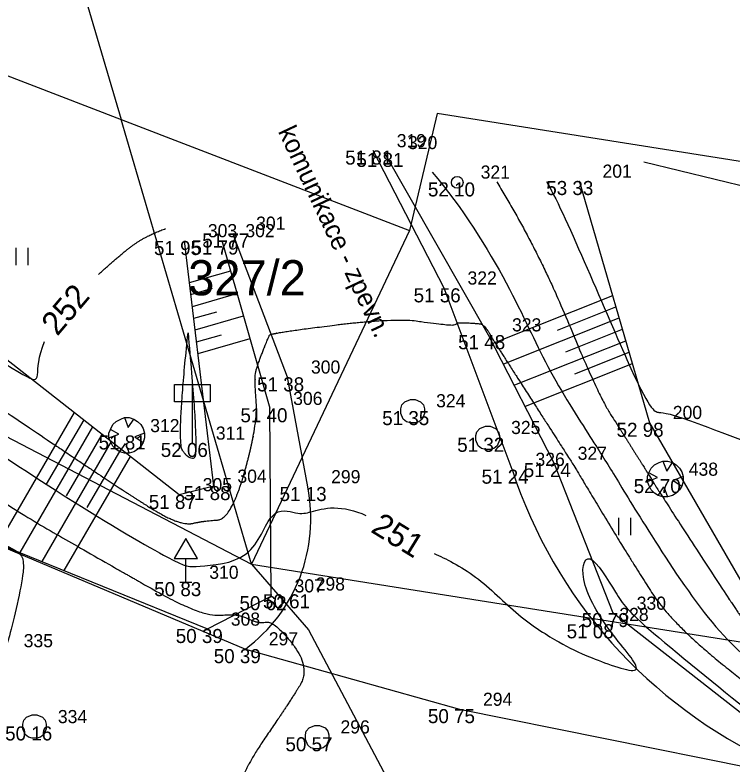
# Model space of a CAD drawing. Extents: x -704057 to -703795, y -1008732 to -1008584.
# Drawn here: x -703998.45 to -703983.13, y -1008647.96 to -1008631.96 of the extents above; entities that cross this region are included whole.
import ezdxf

# ---------------------------------------------------------------- set-up
doc = ezdxf.new("R2010")
doc.units = 0
for name, color, linetype in [('Z_body', 7, 'Continuous'), ('Z_body_cisla', 7, 'Continuous'), ('Z_body_vysky', 7, 'Continuous'), ('Z_dopravni_znaceni', 7, 'Continuous'), ('Z_katastr_cisla_pozemkove', 7, 'Continuous'), ('Z_katastr_hranice', 7, 'Continuous'), ('Z_katastr_hranice_KU', 7, 'Continuous'), ('Z_katastr_vnitrni_kresba', 7, 'Continuous'), ('Z_komunikace_zpevn_pl', 7, 'Continuous'), ('Z_popis', 7, 'Continuous'), ('Z_site_znaky_kanalizace', 7, 'Continuous'), ('Z_sloupky_ocel', 7, 'Continuous'), ('Z_teren_hrany_paty', 7, 'Continuous'), ('Z_vrstevnice_hlavni', 7, 'Continuous'), ('Z_vrstevnice_popis', 7, 'Continuous'), ('Z_vrstevnice_vedlejsi', 7, 'Continuous'), ('Z_zelen_jednotliva', 7, 'Continuous')]:
    doc.layers.add(name, color=color, linetype=linetype)

# ---------------------------------------------------------------- blocks, each defined once
blk = doc.blocks.new('POINT_DISPLAY')
blk.add_line((0, 0), (0, 0))
blk = doc.blocks.new('Z23')
for p, q in [((-0.23, 0.3), (-0.13, 0.35)), ((-0.13, 0.35), (-0.05, 0.38)), ((-0.05, 0.38), (0.05, 0.38)), ((-0.05, 0.38), (0.03, 0.17)), ((0.03, 0.17), (0.15, 0.35)), ((0.05, 0.38), (0.15, 0.35)), ((0.15, 0.35), (0.23, 0.3)), ((-0.35, 0.13), (-0.3, 0.23)), ((-0.3, 0.23), (-0.23, 0.3)), ((0.23, 0.3), (0.3, 0.23)), ((0.3, 0.23), (0.35, 0.15)), ((-0.38, 0.05), (-0.35, 0.13)), ((-0.38, -0.05), (-0.38, 0.05)), ((-0.38, -0.05), (-0.17, 0.03)), ((-0.17, 0.03), (-0.35, 0.13)), ((0.38, 0.05), (0.17, -0.03)), ((0.35, 0.15), (0.38, 0.05)), ((0.38, 0.05), (0.38, -0.05)), ((-0.35, -0.13), (-0.38, -0.05)), ((-0.3, -0.23), (-0.35, -0.13)), ((0.17, -0.03), (0.35, -0.15)), ((0.35, -0.15), (0.3, -0.23)), ((0.38, -0.05), (0.35, -0.15)), ((-0.23, -0.3), (-0.3, -0.23)), ((-0.15, -0.35), (-0.23, -0.3)), ((-0.15, -0.35), (-0.03, -0.17)), ((-0.03, -0.17), (0.05, -0.38)), ((0.23, -0.3), (0.15, -0.35)), ((0.3, -0.23), (0.23, -0.3)), ((-0.05, -0.38), (-0.15, -0.35)), ((0.05, -0.38), (-0.05, -0.38)), ((0.15, -0.35), (0.05, -0.38))]:
    blk.add_line(p, q)
blk = doc.blocks.new('Z620')
for p, q in [((-0.23, 0.13), (-0.17, 0.2)), ((-0.17, 0.2), (-0.05, 0.25)), ((-0.05, 0.25), (0.05, 0.25)), ((0.05, 0.25), (0.17, 0.2)), ((0.17, 0.2), (0.23, 0.13)), ((-0.25, 0.05), (-0.23, 0.13)), ((-0.25, -0.05), (-0.25, 0.05)), ((0.23, 0.13), (0.25, 0.05)), ((0.25, 0.05), (0.25, -0.05)), ((-0.2, -0.17), (-0.25, -0.05)), ((0.25, -0.05), (0.2, -0.17)), ((-0.13, -0.23), (-0.2, -0.17)), ((-0.05, -0.25), (-0.13, -0.23)), ((0.05, -0.25), (-0.05, -0.25)), ((0.13, -0.23), (0.05, -0.25)), ((0.2, -0.17), (0.13, -0.23))]:
    blk.add_line(p, q)
blk = doc.blocks.new('Z527')
for p, q in [((0, 0.93), (-0.25, 0.5)), ((0.25, 0.5), (0, 0.93)), ((-0.25, 0.5), (0.25, 0.5)), ((0, 0), (0, 0.5)), ((-0.13, 0), (0.13, 0))]:
    blk.add_line(p, q)
blk = doc.blocks.new('Z57')
for p, q in [((-0.38, 1.25), (0.38, 1.25)), ((-0.38, 0.88), (-0.38, 1.25)), ((0, 0), (0, 1.25)), ((0.38, 1.25), (0.38, 0.88)), ((0.38, 0.88), (-0.38, 0.88))]:
    blk.add_line(p, q)
blk = doc.blocks.new('Z15')
blk.add_circle((0, 0), 0.125)
blk = doc.blocks.new('Z306')
for p, q in [((-0.13, 0.17), (-0.13, -0.2)), ((0.13, 0.17), (0.13, -0.2))]:
    blk.add_line(p, q)

msp = doc.modelspace()

# ---------------------------------------------------------------- linework, layer by layer
at = {"layer": 'Z_katastr_hranice'}
for p, q in [((-704002.96, -1008611.05), (-703996.18, -1008634.19)), ((-703989.44, -1008634.06), (-703990.03, -1008636.56)), ((-703948.06, -1008640.63), (-703989.44, -1008634.06)), ((-703996.18, -1008634.19), (-703990.03, -1008636.56)), ((-703993.4, -1008643.68), (-703996.18, -1008634.19)), ((-703990.03, -1008636.56), (-703993.4, -1008643.68)), ((-703993.4, -1008643.68), (-703944.4, -1008651.45))]:
    msp.add_line(p, q, dxfattribs=at)
at = {"layer": 'Z_katastr_hranice_KU'}
for p, q in [((-703999.92, -1008640.28), (-703993.4, -1008643.68)), ((-703993.4, -1008643.68), (-703992.18, -1008645.08)), ((-703992.18, -1008645.08), (-703989.65, -1008649.86))]:
    msp.add_line(p, q, dxfattribs=at)
at = {"layer": 'Z_katastr_vnitrni_kresba'}
msp.add_line((-704003.46, -1008631.38), (-703996.18, -1008634.19), dxfattribs=at)
at = {"layer": 'Z_komunikace_zpevn_pl'}
for p, q in [((-703989.29, -1008637.79), (-703990.8, -1008634.85)), ((-703992.63, -1008639.69), (-703993.8, -1008636.62)), ((-703987.84, -1008641.66), (-703989.29, -1008637.79)), ((-703992.2, -1008642.03), (-703992.63, -1008639.69)), ((-704000.17, -1008642.69), (-703993.53, -1008645.49)), ((-703993.53, -1008645.49), (-703988.96, -1008646.77)), ((-703988.96, -1008646.77), (-703980.49, -1008648.48))]:
    msp.add_line(p, q, dxfattribs=at)
for centre, radius, start, end in [((-703977.91, -1008638.41), 10.448, 198.1269, 245.2768), ((-703995.6, -1008642.71), 3.467, 306.6532, 11.294)]:
    msp.add_arc(centre, radius, start, end, dxfattribs=at)
at = {"layer": 'Z_teren_hrany_paty'}
for p, q in [((-703988.34, -1008638.79), (-703990.56, -1008634.9)), ((-703986.41, -1008635.5), (-703984.91, -1008640.66)), ((-703994.2, -1008642.01), (-703994.83, -1008636.78)), ((-703994.03, -1008636.77), (-703993.01, -1008640.35)), ((-703994.94, -1008642.2), (-704001.6, -1008636.98)), ((-703994.72, -1008637.67), (-703993.84, -1008637.42)), ((-703994.69, -1008637.92), (-703994.23, -1008637.79)), ((-703994.66, -1008638.18), (-703993.71, -1008637.9)), ((-703985.7, -1008637.95), (-703988.25, -1008638.97)), ((-703985.63, -1008638.19), (-703986.88, -1008638.69)), ((-703994.63, -1008638.43), (-703994.14, -1008638.29)), ((-703994.6, -1008638.68), (-703993.57, -1008638.38)), ((-703985.56, -1008638.43), (-703988.02, -1008639.41)), ((-703985.49, -1008638.67), (-703986.7, -1008639.15)), ((-703994.57, -1008638.93), (-703994.04, -1008638.78)), ((-703994.54, -1008639.18), (-703993.43, -1008638.86)), ((-703986.94, -1008641.52), (-703988.34, -1008638.79)), ((-703985.42, -1008638.92), (-703987.79, -1008639.86)), ((-703985.35, -1008639.16), (-703986.51, -1008639.62)), ((-703985.28, -1008639.4), (-703987.56, -1008640.31)), ((-703997.18, -1008640.44), (-703998.81, -1008643.24)), ((-703992.98, -1008644.36), (-703993.01, -1008640.35)), ((-703996.98, -1008640.6), (-703997.78, -1008641.97)), ((-703996.79, -1008640.75), (-703998.34, -1008643.43)), ((-703984.91, -1008640.66), (-703982.03, -1008645.65)), ((-703996.59, -1008640.91), (-703997.35, -1008642.22)), ((-703996.39, -1008641.06), (-703997.87, -1008643.62)), ((-703996.19, -1008641.22), (-703996.91, -1008642.47)), ((-703995.99, -1008641.38), (-703997.4, -1008643.81)), ((-703985.68, -1008644.72), (-703986.94, -1008641.52)), ((-703994.2, -1008642.01), (-703994.94, -1008642.2)), ((-704000.17, -1008642.69), (-703994.34, -1008645.06)), ((-703994.34, -1008645.06), (-703992.98, -1008644.36)), ((-703982.11, -1008647.52), (-703985.68, -1008644.72))]:
    msp.add_line(p, q, dxfattribs=at)
at = {"layer": 'Z_vrstevnice_hlavni'}
msp.add_open_spline([(-703994.753, -1008638.739), (-703994.996, -1008641.052), (-703994.748, -1008641.441), (-703994.507, -1008641.397), (-703994.753, -1008638.739)], degree=2, dxfattribs=at)
at = {"layer": 'Z_vrstevnice_popis'}
for points, degree in [([(-704008.891, -1008633.225), (-704007.19, -1008634.58), (-704001.968, -1008637.528), (-704001.463, -1008637.527), (-703997.448, -1008640.245), (-703998.103, -1008639.589), (-703997.814, -1008638.926)], 3), ([(-704009.834, -1008633.947), (-704008.639, -1008634.898), (-704007.097, -1008636.135), (-704003.977, -1008638.277), (-704003.231, -1008638.819), (-704001.631, -1008639.907), (-704000.867, -1008639.906), (-703997.17, -1008642.409), (-703994.823, -1008643.756), (-703994.703, -1008643.728), (-703993.348, -1008643.651), (-703992.995, -1008642.406), (-703992.399, -1008642.624), (-703992.166, -1008642.575), (-703991.675, -1008642.426), (-703991.193, -1008642.529), (-703990.961, -1008642.637)], 3), ([(-704010.777, -1008634.669), (-704010.089, -1008635.217), (-704007.004, -1008637.69), (-704006.178, -1008638.257), (-704004.336, -1008639.596), (-704000.382, -1008642.286), (-704000.271, -1008642.286), (-703999.734, -1008642.649), (-703999.257, -1008642.923), (-703998.4, -1008643.409), (-703998.154, -1008643.54), (-703998.629, -1008645.519), (-703998.717, -1008645.615), (-703998.773, -1008645.668), (-703999.967, -1008646.451), (-704000.248, -1008646.631)], 3), ([(-703989.544, -1008635.313), (-703988.902, -1008636.056), (-703987.798, -1008637.865), (-703987.151, -1008639.438), (-703986.053, -1008641.144), (-703985.706, -1008641.697), (-703984.977, -1008642.908), (-703983.536, -1008645.121), (-703982.31, -1008646.105), (-703982.063, -1008646.423), (-703981.066, -1008646.966), (-703978.397, -1008647.285), (-703975.56, -1008647.648), (-703973.643, -1008647.827), (-703973.517, -1008647.838)], 3), ([(-703987.108, -1008635.508), (-703986.754, -1008636.087), (-703984.996, -1008640.365), (-703984.718, -1008640.456), (-703984.363, -1008640.44), (-703980.63, -1008641.987), (-703979.311, -1008641.778), (-703978.799, -1008641.628)], 3), ([(-703996.666, -1008637.496), (-703996.184, -1008637.054), (-703995.648, -1008636.67), (-703995.232, -1008636.515)], 2), ([(-703989.503, -1008643.449), (-703989.267, -1008643.557), (-703988.594, -1008643.878), (-703987.719, -1008644.81), (-703986.755, -1008645.399), (-703986.308, -1008645.619), (-703984.807, -1008646.186), (-703985.704, -1008645.225), (-703986.427, -1008644.081), (-703986.268, -1008643.227), (-703985.558, -1008644.406), (-703985.308, -1008644.79), (-703982.136, -1008647.335), (-703982.104, -1008647.377), (-703980.996, -1008647.981), (-703981.138, -1008648.096), (-703981.236, -1008648.238), (-703982.91, -1008647.991), (-703984.29, -1008649.466), (-703985.601, -1008651.032), (-703985.434, -1008652.571), (-703985.359, -1008653.111)], 3)]:
    msp.add_open_spline(points, degree=degree, dxfattribs=at)
at = {"layer": 'Z_vrstevnice_vedlejsi'}
msp.add_line((-703981.434, -1008635.969), (-703985.029, -1008635.098), dxfattribs=at)
for points in [[(-704009.362, -1008633.586), (-704007.915, -1008634.739), (-704007.143, -1008635.358), (-704002.876, -1008638.286), (-704002.679, -1008638.43), (-704002.255, -1008638.718), (-704001.165, -1008638.717), (-703995.889, -1008642.289), (-703994.89, -1008642.862), (-703994.417, -1008642.752), (-703993.832, -1008642.719), (-703993.258, -1008640.696), (-703993.341, -1008639.701), (-703993.272, -1008639.432), (-703993.04, -1008638.835), (-703992.99, -1008638.745), (-703990.403, -1008638.423), (-703989.481, -1008638.539), (-703989.058, -1008638.588), (-703989.018, -1008638.516), (-703988.578, -1008638.54), (-703988.475, -1008638.554), (-703988.362, -1008638.685), (-703988.319, -1008638.754), (-703988.294, -1008638.815), (-703986.637, -1008641.391), (-703986.518, -1008641.581), (-703985.267, -1008643.657), (-703984.422, -1008644.955), (-703982.223, -1008646.72), (-703982.083, -1008646.9), (-703980.47, -1008647.779), (-703979.335, -1008647.914), (-703971.793, -1008648.878), (-703969.312, -1008649.063), (-703968.076, -1008649.117), (-703960.948, -1008649.919), (-703959.282, -1008650.186), (-703958.493, -1008650.28), (-703957.367, -1008650.455), (-703955.116, -1008650.684), (-703950.816, -1008651.182), (-703948.3, -1008651.463), (-703946.953, -1008651.576), (-703945.397, -1008651.505), (-703943.023, -1008651.703), (-703939.161, -1008651.987), (-703938.27, -1008652.079), (-703937.191, -1008652.194), (-703934.147, -1008651.524), (-703931.028, -1008650.815), (-703930.717, -1008650.764), (-703928.94, -1008650.83), (-703928.501, -1008650.751), (-703928.424, -1008650.713), (-703928.413, -1008650.708), (-703928.266, -1008650.724), (-703926.027, -1008648.737), (-703920.5, -1008648.624), (-703915.824, -1008649.925), (-703908.88, -1008649.843), (-703904.651, -1008650.155), (-703897.103, -1008651.333), (-703893.743, -1008651.997), (-703889.99, -1008652.252), (-703881.693, -1008653.228), (-703874.656, -1008652.961), (-703868.448, -1008652.365), (-703859.857, -1008652.906), (-703856.36, -1008653.001), (-703843.765, -1008653.766), (-703842.17, -1008653.801), (-703841.143, -1008653.824), (-703831.904, -1008654.28)], [(-704010.305, -1008634.308), (-704009.364, -1008635.058), (-704007.05, -1008636.913), (-704005.077, -1008638.267), (-704003.784, -1008639.207), (-704001.007, -1008641.096), (-704000.569, -1008641.096), (-703998.452, -1008642.529), (-703996.572, -1008643.608), (-703994.455, -1008644.81), (-703993.69, -1008644.725), (-703993.267, -1008644.95), (-703992.917, -1008644.879), (-703992.134, -1008645.881), (-703992.595, -1008646.639), (-703993.503, -1008647.958), (-703993.68, -1008648.547), (-703995.276, -1008650.526), (-703996.236, -1008651.302), (-703996.767, -1008651.84), (-703996.931, -1008651.871), (-703997.503, -1008651.617), (-703999.042, -1008651.416), (-703999.451, -1008652.579)], [(-703988.164, -1008635.52), (-703987.276, -1008636.976), (-703986.008, -1008640.062), (-703985.47, -1008640.897), (-703984.895, -1008641.813), (-703984.686, -1008642.159), (-703982.65, -1008645.287), (-703982.397, -1008645.49), (-703982.043, -1008645.946), (-703981.661, -1008646.154), (-703977.458, -1008646.656), (-703976.772, -1008646.743), (-703972.443, -1008647.066), (-703969.747, -1008647.327), (-703967.111, -1008646.193), (-703965.337, -1008645.561), (-703960.636, -1008644.491), (-703957.873, -1008644.043), (-703955.63, -1008643.808), (-703952.03, -1008643.609), (-703943.212, -1008644.531), (-703942.275, -1008644.62), (-703942.236, -1008644.645), (-703942.208, -1008644.623), (-703942.168, -1008644.583), (-703942.126, -1008644.569), (-703941.982, -1008644.492), (-703939.179, -1008642.975), (-703937.245, -1008642.629)]]:
    msp.add_open_spline(points, degree=2, dxfattribs=at)

# ---------------------------------------------------------------- block references
at = {"layer": 'Z_body'}
for p in [(-703990.8, -1008634.85), (-703990.56, -1008634.9), (-703986.41, -1008635.5), (-703989.01, -1008635.53), (-703993.8, -1008636.62), (-703994.83, -1008636.78), (-703994.03, -1008636.77), (-703989.29, -1008637.79), (-703988.34, -1008638.79), (-703992.63, -1008639.69), (-703993.01, -1008640.35), (-703989.96, -1008640.41), (-703984.91, -1008640.66), (-703996.06, -1008640.93), (-703994.66, -1008641.09), (-703988.36, -1008640.98), (-703986.94, -1008641.52), (-703987.84, -1008641.66), (-703984.57, -1008641.86), (-703994.2, -1008642.01), (-703992.2, -1008642.03), (-703994.94, -1008642.2), (-703994.8, -1008644.06), (-703992.98, -1008644.36), (-703992.53, -1008644.32), (-703985.68, -1008644.72), (-703994.34, -1008645.06), (-703986.05, -1008644.96), (-703993.53, -1008645.49), (-703988.96, -1008646.77), (-703998.03, -1008647.14), (-703992, -1008647.37)]:
    msp.add_blockref('POINT_DISPLAY', p, dxfattribs=at)
at = {"layer": 'Z_dopravni_znaceni'}
for name, p in [('Z57', (-703994.66, -1008641.09)), ('Z527', (-703994.8, -1008644.06))]:
    msp.add_blockref(name, p, dxfattribs=at)
at = {"layer": 'Z_popis'}
for p in [(-703998.3, -1008637.1), (-703985.44, -1008642.86)]:
    msp.add_blockref('Z306', p, dxfattribs=at)
at = {"layer": 'Z_site_znaky_kanalizace'}
for p in [(-703989.96, -1008640.41), (-703988.36, -1008640.98), (-703998.03, -1008647.14), (-703992, -1008647.37)]:
    msp.add_blockref('Z620', p, dxfattribs=at)
at = {"layer": 'Z_sloupky_ocel'}
msp.add_blockref('Z15', (-703989.01, -1008635.53), dxfattribs=at)
at = {"layer": 'Z_zelen_jednotliva'}
for p in [(-703996.06, -1008640.93), (-703984.57, -1008641.86)]:
    msp.add_blockref('Z23', p, dxfattribs=at)

# ---------------------------------------------------------------- texts
at = {"layer": 'Z_body_cisla'}
for s, p in [('319', (-703990.3, -1008634.78)), ('320', (-703990.06, -1008634.82)), ('321', (-703988.51, -1008635.45)), ('201', (-703985.91, -1008635.43)), ('301', (-703993.3, -1008636.54)), ('303', (-703994.33, -1008636.7)), ('302', (-703993.53, -1008636.7)), ('322', (-703988.79, -1008637.71)), ('323', (-703987.84, -1008638.71)), ('300', (-703992.13, -1008639.61)), ('306', (-703992.51, -1008640.28)), ('324', (-703989.46, -1008640.33)), ('200', (-703984.41, -1008640.58)), ('312', (-703995.56, -1008640.86)), ('325', (-703987.86, -1008640.9)), ('311', (-703994.16, -1008641.02)), ('327', (-703986.44, -1008641.45)), ('326', (-703987.34, -1008641.58)), ('438', (-703984.07, -1008641.79)), ('304', (-703993.7, -1008641.94)), ('299', (-703991.7, -1008641.95)), ('305', (-703994.44, -1008642.12)), ('310', (-703994.3, -1008643.99)), ('298', (-703992.03, -1008644.24)), ('307', (-703992.48, -1008644.28)), ('330', (-703985.18, -1008644.65)), ('328', (-703985.55, -1008644.89)), ('308', (-703993.84, -1008644.99)), ('335', (-703998.26, -1008645.45)), ('297', (-703993.03, -1008645.41)), ('294', (-703988.46, -1008646.7)), ('334', (-703997.53, -1008647.07)), ('296', (-703991.5, -1008647.29))]:
    msp.add_text(s, height=0.28, dxfattribs=at).set_placement(p)
at = {"layer": 'Z_body_vysky'}
for s, p in [('51 81', (-703991.4, -1008635.15)), ('51 81', (-703991.16, -1008635.2)), ('53 33', (-703987.11, -1008635.8)), ('52 10', (-703989.635, -1008635.83)), ('51 77', (-703994.45, -1008636.92)), ('51 95', (-703995.48, -1008637.08)), ('51 79', (-703994.68, -1008637.07)), ('51 56', (-703989.94, -1008638.09)), ('51 48', (-703988.99, -1008639.09)), ('51 38', (-703993.28, -1008639.99)), ('51 40', (-703993.635, -1008640.65)), ('51 35', (-703990.61, -1008640.71)), ('52 98', (-703985.61, -1008640.96)), ('51 81', (-703996.66, -1008641.23)), ('52 06', (-703995.335, -1008641.39)), ('51 32', (-703989.01, -1008641.28)), ('51 24', (-703987.59, -1008641.82)), ('51 24', (-703988.49, -1008641.96)), ('52 70', (-703985.245, -1008642.16)), ('51 88', (-703994.85, -1008642.31)), ('51 13', (-703992.8, -1008642.33)), ('51 87', (-703995.59, -1008642.5)), ('50 83', (-703995.475, -1008644.36)), ('50 62', (-703993.655, -1008644.66)), ('50 61', (-703993.155, -1008644.62)), ('50 79', (-703986.355, -1008645.02)), ('50 39', (-703995.015, -1008645.36)), ('51 08', (-703986.675, -1008645.26)), ('50 39', (-703994.205, -1008645.79)), ('50 75', (-703989.635, -1008647.07)), ('50 16', (-703998.655, -1008647.44)), ('50 57', (-703992.675, -1008647.67))]:
    msp.add_text(s, height=0.3, dxfattribs=at).set_placement(p)
at = {"layer": 'Z_katastr_cisla_pozemkove'}
msp.add_text('327/2', height=0.75, dxfattribs=at).set_placement((-703994.75, -1008637.94))
at = {"layer": 'Z_popis'}
msp.add_text('komunikace - zpevn.', height=0.4, rotation=295.2, dxfattribs=at).set_placement((-703992.84, -1008634.44))
at = {"layer": 'Z_vrstevnice_popis'}
for s, rotation, p in [('252', 49.8394, (-703997.543, -1008638.827)), ('251', 328.4023, (-703990.877, -1008642.978))]:
    msp.add_text(s, height=0.5, rotation=rotation, dxfattribs=at).set_placement(p)

doc.saveas('drawing.dxf')
